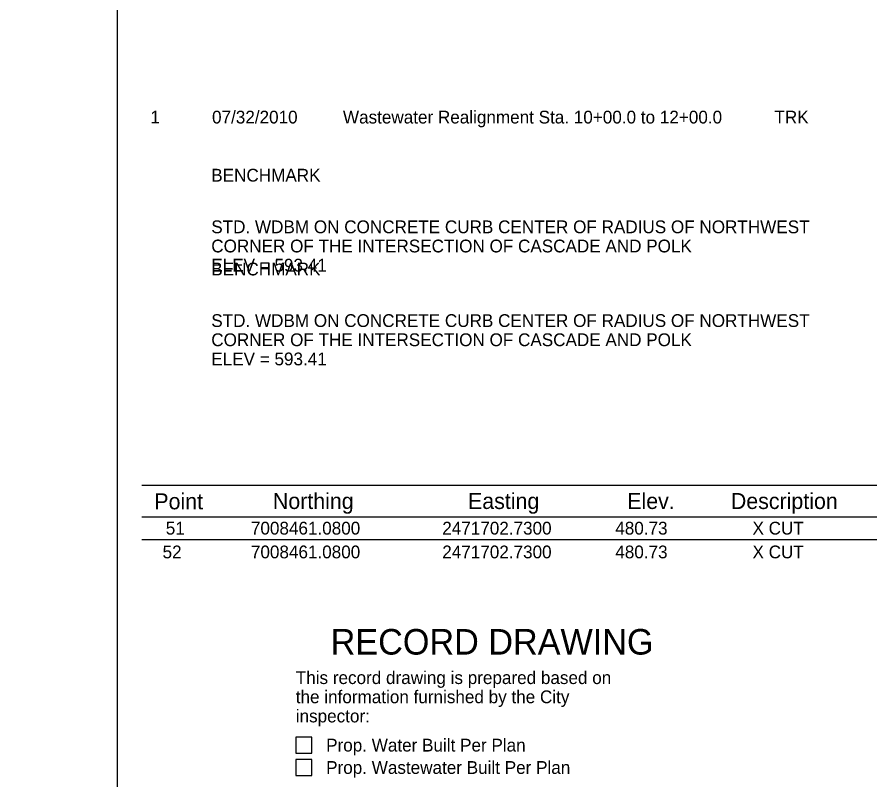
# Model space of a CAD drawing. Extents: x -2178 to -1318, y -1569 to -1077.
# Drawn here: x -1473.9 to -1339.4, y -1445.4 to -1326.1 of the extents above; entities that cross this region are included whole.
import ezdxf

# ---------------------------------------------------------------- set-up
doc = ezdxf.new("R2010")
doc.units = 0
for name, color, linetype in [('G_BORDER', 7, 'Continuous'), ('G_SHEET_EDGE', 7, 'Continuous'), ('G_SIGNATURE BLOCK', 7, 'Continuous')]:
    doc.layers.add(name, color=color, linetype=linetype)

msp = doc.modelspace()

# ---------------------------------------------------------------- linework, layer by layer
at = {"layer": 'G_BORDER'}
for p, q in [((-1454.39, -1399.26), (-1339.39, -1399.26)), ((-1454.39, -1404.26), (-1339.39, -1404.26)), ((-1454.39, -1407.76), (-1339.39, -1407.76))]:
    msp.add_line(p, q, dxfattribs=at)
at = {"layer": 'G_SHEET_EDGE'}
msp.add_lwpolyline([(-2178.18, -1562.44), (-1458.18, -1562.44), (-1458.18, -1082.44), (-2178.18, -1082.44)], close=True, dxfattribs=at)
at = {"layer": 'G_SIGNATURE BLOCK'}
for points in [[(-1430.3, -1441.21), (-1427.8, -1441.21), (-1427.8, -1438.71), (-1430.3, -1438.71)], [(-1430.3, -1444.71), (-1427.8, -1444.71), (-1427.8, -1442.21), (-1430.3, -1442.21)]]:
    msp.add_lwpolyline(points, close=True, dxfattribs=at)

# ---------------------------------------------------------------- texts
at = {"layer": 'G_BORDER'}
for s, height, p in [('1', 2, (-1453.04, -1342.69)), ('07/32/2010', 2, (-1443.4, -1342.69)), ('Wastewater Realignment Sta. 10+00.0 to 12+00.0', 2, (-1422.92, -1342.69)), ('TRK', 2, (-1355.41, -1342.69)), ('BENCHMARK', 2, (-1443.52, -1351.78)), ('STD. WDBM ON CONCRETE CURB CENTER OF RADIUS OF NORTHWEST', 2, (-1443.52, -1359.86)), ('CORNER OF THE INTERSECTION OF CASCADE AND POLK', 2, (-1443.52, -1362.86)), ('ELEV = 593.41', 2, (-1443.52, -1365.86)), ('BENCHMARK', 2, (-1443.52, -1366.46)), ('STD. WDBM ON CONCRETE CURB CENTER OF RADIUS OF NORTHWEST', 2, (-1443.52, -1374.53)), ('CORNER OF THE INTERSECTION OF CASCADE AND POLK', 2, (-1443.52, -1377.53)), ('ELEV = 593.41', 2, (-1443.52, -1380.53)), ('Point', 2.5, (-1452.43, -1403.06)), ('Northing', 2.5, (-1433.88, -1403.01)), ('Easting', 2.5, (-1403.35, -1403.01)), ('Elev.', 2.5, (-1378.44, -1403.01)), ('Description', 2.5, (-1362.23, -1403.01)), ('51', 2, (-1450.64, -1407.01)), ('7008461.0800', 2, (-1437.32, -1407.01)), ('2471702.7300', 2, (-1407.38, -1407.01)), ('480.73', 2, (-1380.31, -1407.01)), ('X CUT', 2, (-1358.84, -1407.01)), ('52', 2, (-1451.14, -1410.73)), ('7008461.0800', 2, (-1437.32, -1410.73)), ('2471702.7300', 2, (-1407.38, -1410.73)), ('480.73', 2, (-1380.31, -1410.73)), ('X CUT', 2, (-1358.84, -1410.73))]:
    msp.add_text(s, height=height, dxfattribs=at).set_placement(p)
at = {"layer": 'G_SIGNATURE BLOCK'}
msp.add_text('RECORD DRAWING', height=4, rotation=360, dxfattribs=at).set_placement((-1424.84, -1425.79))
for s, p in [('This record drawing is prepared based on', (-1430.3, -1430.4)), ('the information furnished by the City', (-1430.3, -1433.4)), ('inspector:', (-1430.3, -1436.4)), ('Prop. Water Built Per Plan', (-1425.55, -1440.96)), ('Prop. Wastewater Built Per Plan', (-1425.55, -1444.46))]:
    msp.add_text(s, height=2, dxfattribs=at).set_placement(p)

doc.saveas('drawing.dxf')
